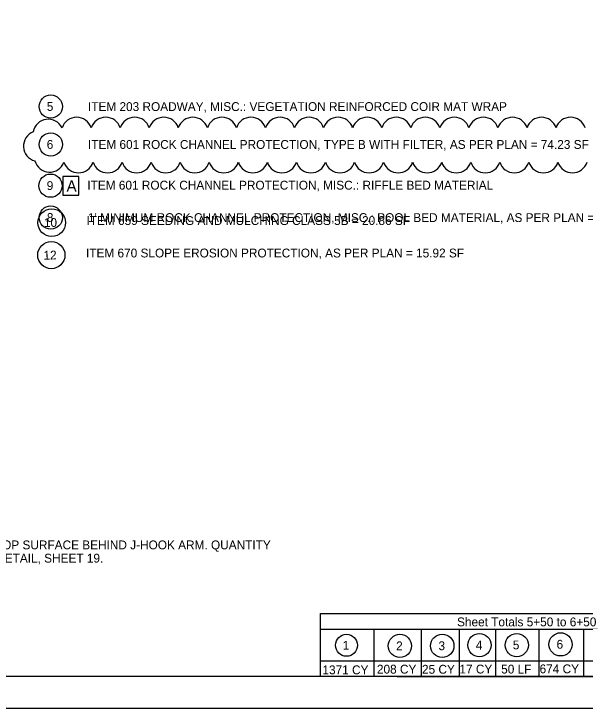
# Model space of a CAD drawing. Extents: x -433 to 34, y -184 to 22.
# Drawn here: x 20.18 to 29.23, y 0 to 11 of the extents above; entities that cross this region are included whole.
import ezdxf

# ---------------------------------------------------------------- set-up
doc = ezdxf.new("R2010")
doc.units = 0
for name, color, linetype in [('CS-ALGN-TEXT', 7, 'Continuous'), ('CS-ANNO', 7, 'Continuous'), ('CS-ANNO-MATC', 7, 'Continuous'), ('CS-ANNO-MATC-TEXT', 7, 'Continuous'), ('CS-ANNO-TABL', 7, 'Continuous')]:
    doc.layers.add(name, color=color, linetype=linetype)

msp = doc.modelspace()

# ---------------------------------------------------------------- linework, layer by layer
at = {"layer": 'CS-ALGN-TEXT'}
for p, q in [((25.033, 0.5), (25.033, 1.5)), ((25.033, 1.5), (32, 1.5)), ((25.033, 1.25), (32, 1.25)), ((25.884, 0.499), (25.884, 1.249)), ((26.634, 0.5), (26.634, 1.25)), ((27.239, 0.5), (27.239, 1.25)), ((27.812, 0.5), (27.812, 1.25)), ((28.496, 0.5), (28.496, 1.25)), ((29.208, 0.5), (29.208, 1.25)), ((25.033, 0.75), (32, 0.75)), ((26.25, 0.5), (32, 0.5))]:
    msp.add_line(p, q, dxfattribs=at)
at = {"layer": 'CS-ANNO'}
msp.add_lwpolyline([(0, 0), (34, 0), (34, 22), (0, 22)], close=True, dxfattribs=at)
at = {"layer": 'CS-ANNO-MATC'}
msp.add_lwpolyline([(1.5, 21.5), (33.5, 21.5), (33.5, 0.5), (1.5, 0.5)], close=True, dxfattribs=at)
at = {"layer": 'CS-ANNO-MATC-TEXT'}
msp.add_lwpolyline([(20.954, 8.126), (21.209, 8.126), (21.209, 8.422), (20.954, 8.422)], close=True, dxfattribs=at)
for centre, radius in [((20.763, 9.531), 0.184), ((20.763, 8.931), 0.184), ((20.759, 8.278), 0.184), ((20.778, 7.692), 0.218), ((20.772, 7.179), 0.216), ((25.447, 0.996), 0.174), ((26.293, 0.986), 0.184), ((26.964, 0.987), 0.185), ((27.552, 0.998), 0.184), ((28.143, 0.999), 0.184), ((28.838, 1.01), 0.184)]:
    msp.add_circle(centre, radius, dxfattribs=at)
for centre, start, end in [((21.173, 9.121), 17.5, 162.5), ((21.633, 9.121), 17.5, 162.5), ((22.093, 9.121), 17.5, 162.5), ((22.553, 9.121), 17.5, 162.5), ((23.013, 9.121), 17.5, 162.5), ((23.474, 9.121), 17.5, 162.5), ((23.934, 9.121), 17.5, 162.5), ((24.394, 9.121), 17.5, 162.5), ((24.854, 9.121), 17.5, 162.5), ((25.314, 9.121), 17.5, 162.5), ((25.775, 9.121), 17.5, 162.5), ((26.235, 9.121), 17.5, 162.5), ((26.695, 9.121), 17.5, 162.5), ((27.155, 9.121), 17.5, 162.5), ((27.615, 9.121), 17.5, 162.5), ((28.076, 9.121), 17.5, 162.5), ((28.536, 9.121), 17.5, 162.5), ((28.996, 9.121), 17.5, 162.5), ((20.724, 9.09), 25.3582, 170.3582), ((20.572, 8.905), 110.709, 255.709), ((20.746, 8.733), 194.7556, 339.7556), ((21.202, 8.722), 197.5, 342.5), ((21.663, 8.722), 197.5, 342.5), ((22.123, 8.722), 197.5, 342.5), ((22.583, 8.722), 197.5, 342.5), ((23.043, 8.722), 197.5, 342.5), ((23.503, 8.722), 197.5, 342.5), ((23.964, 8.722), 197.5, 342.5), ((24.424, 8.722), 197.5, 342.5), ((24.884, 8.722), 197.5, 342.5), ((25.344, 8.722), 197.5, 342.5), ((25.804, 8.722), 197.5, 342.5), ((26.265, 8.722), 197.5, 342.5), ((26.725, 8.722), 197.5, 342.5), ((27.185, 8.722), 197.5, 342.5), ((27.645, 8.722), 197.5, 342.5), ((28.105, 8.722), 197.5, 342.5), ((28.566, 8.722), 197.5, 342.5), ((29.026, 8.723), 197.7888, 342.7888)]:
    msp.add_arc(centre, 0.241, start, end, dxfattribs=at)
at = {"layer": 'CS-ANNO-TABL'}
msp.add_circle((20.763, 7.772), 0.184, dxfattribs=at)

# ---------------------------------------------------------------- texts
at = {"layer": 'CS-ALGN-TEXT'}
msp.add_text('Sheet Totals 5+50 to 6+50', height=0.14, dxfattribs=at).set_placement((27.198, 1.296))
at = {"layer": 'CS-ANNO-MATC-TEXT'}
for s, height, p in [('5', 0.14, (20.7, 9.463)), ('ITEM 203 ROADWAY, MISC.: VEGETATION REINFORCED COIR MAT WRAP', 0.14, (21.352, 9.461)), ('6', 0.14, (20.699, 8.862)), ('ITEM 601 ROCK CHANNEL PROTECTION, TYPE B WITH FILTER, AS PER PLAN = 74.23 SF', 0.14, (21.352, 8.861)), ('A', 0.177, (21.014, 8.185)), ('9', 0.14, (20.699, 8.209)), ('ITEM 601 ROCK CHANNEL PROTECTION, MISC.: RIFFLE BED MATERIAL', 0.14, (21.342, 8.216)), ('ITEM 659 SEEDING AND MULCHING CLASS 5B = 20.86 SF', 0.14, (21.329, 7.655)), ('ITEM 670 SLOPE EROSION PROTECTION, AS PER PLAN = 15.92 SF', 0.14, (21.321, 7.141)), ('INCORPORATE INTO RCP TYPE B, FILLING VOIDS IN TOP SURFACE BEHIND J-HOOK ARM. QUANTITY ', 0.14, (15.104, 2.516)), ('FOR THIS WORK PROVIDED IN J-HOOK STRUCTURE DETAIL, SHEET 19.', 0.14, (15.104, 2.306)), ('1', 0.14, (25.386, 0.925)), ('2', 0.14, (26.233, 0.916)), ('3', 0.14, (26.904, 0.918)), ('4', 0.14, (27.495, 0.928)), ('5', 0.14, (28.081, 0.931)), ('6', 0.14, (28.774, 0.941)), ('1371 CY', 0.14, (25.066, 0.536)), ('208 CY', 0.14, (25.929, 0.547)), ('25 CY', 0.14, (26.643, 0.545)), ('17 CY', 0.14, (27.236, 0.549)), ('50 LF', 0.14, (27.897, 0.548)), ('674 CY', 0.14, (28.505, 0.552))]:
    msp.add_text(s, height=height, dxfattribs=at).set_placement(p)
for s, p in [('10', (20.655, 7.621)), ('12', (20.649, 7.106))]:
    msp.add_text(s, height=0.14, rotation=1, dxfattribs=at).set_placement(p)
at = {"layer": 'CS-ANNO-TABL'}
for s, p in [('8', (20.701, 7.703)), ("1' MINIMUM ROCK CHANNEL PROTECTION, MISC.: POOL BED MATERIAL, AS PER PLAN = XX.XX", (21.352, 7.702))]:
    msp.add_text(s, height=0.14, dxfattribs=at).set_placement(p)

doc.saveas('drawing.dxf')
